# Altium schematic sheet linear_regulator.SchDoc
size A3
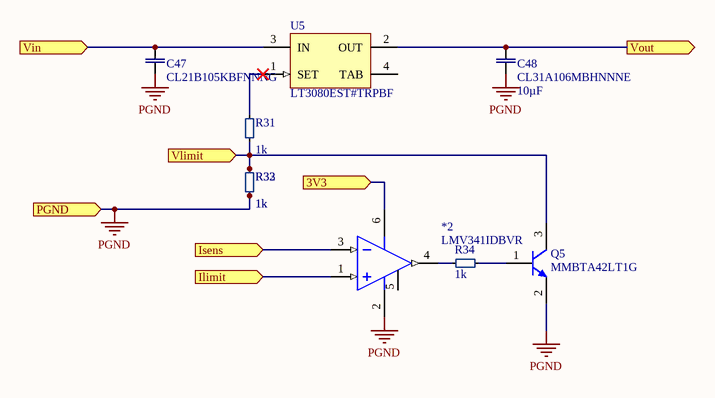
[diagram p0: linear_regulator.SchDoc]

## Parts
*2  LMV341IDBVR  [SOT95P280X145-6N]
C47  CL21B105KBFNNNG  [CAP0805]
C48  CL31A106MBHNNNE  Capacitance: 10µF  [Chip2PinSM127P600-8N]
Q5  MMBTA42LT1G  [ONSC-SOT-23-3-318-08_V]
R31  Resistance: 1k  [SMD_0402(1005)_M]  (hidden comment: RC0402FR-071KL)
R32  Resistance: 1k  [SMD_0402(1005)_M]  (hidden comment: RC0402FR-071KL)
R33  Resistance: 1k  [SMD_0402(1005)_M]  (hidden comment: RC0402FR-071KL)
R34  Resistance: 1k  [SMD_0402(1005)_M]  (hidden comment: RC0402FR-071KL)
U5  LT3080EST#TRPBF  [LT-ST-3-SOT-223_M]

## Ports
3V3 (in), Ilimit (in), Isens (in), PGND (in), Vin (in), Vlimit (in), Vout (out)

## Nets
PGND: *2.2(VEE/GND) C47.1 C48.1 Q5.2(E) R32.1 R33.1 ; port PGND
3V3: *2.6(VCC) ; port 3V3
Ilimit: *2.1(IN1+) ; port Ilimit
Isens: *2.3(IN1-) ; port Isens
Vin: C47.2 U5.3(IN) ; port Vin
Vlimit: Q5.3(C) R31.1 R32.2 R33.2 ; port Vlimit
Vout: C48.2 U5.2(OUT) ; port Vout
Net*2_4: *2.4(OUT1) R34.2
NetQ5_1: Q5.1(B) R34.1
NetR31_2: R31.2 U5.1(SET)

Not connected (* = marked no-connect by the designer): *2 5(!SHDN); U5 4(TAB)

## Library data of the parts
*2 = CMP-ROOT-00000-1: Single Rail-To-Rail Output CMOS Operational Amplifier with Shutdown 6-SOT-23 -40 to 125; Voltage Gain: 116dB; Output Current: 32mA; Number of Channels: 1; Common Mode Rejection Ratio: 56dB; Input Offset Voltage (Vos): 250uV; Bandwidth: 1MHz; Max Supply Voltage: 5.5V; Max Frequency: 1kHz; Output Current per Channel: 113mA; Operating Supply Current: 107uA; Slew Rate: 1V/µs; Input Bias Current: 200pA; Nominal Supply Current: 170uA; Min Supply Voltage: 2.5V
C47 = CMP-0001-00012-4: SAMSUNG ELECTRO-MECHANICS - CL21B105KBFNNNG - MLCC CAPACITORS; Voltage Rating: 50V; Dielectric: X7R; Material: Ceramic; Capacitance: 1µF; Tolerance: 10%
C48 = CMP-0001-00015-2: CAP CER 10UF 50V X5R 1206; Capacitor Type: Ceramic; Tolerance: 20%
Q5 = CMP-ROOT-00016-1: Trans GP BJT NPN 300V 0.5A Automotive 3-Pin SOT-23 T/R; Frequency: 50MHz; Emitter Base Voltage (VEBO): 6V; Number of Elements: 1; Max Collector Current: 500mA; Power Dissipation: 300mW; Max Power Dissipation: 225mW; Collector Emitter Saturation Voltage: 500mV; Element Configuration: Single; hFE Min: 25
R31-R34 = CMP-001-0000-7: Surface Mount Chip Resistor, Thick Film, RC Series, 1 kohm, 62.5 mW, 1%, 50 V, 0402 [1005 Metric]; Temperature Coefficient: 100ppm/°C; Value: 1k; Voltage Rating: 50V; Power Rating: 62.5mW
U5 = CMP-00005-1: IC REG LIN POS ADJ 1.1A SOT223-3; Operating Supply Current: 300uA; Quiescent Current: 500uA; Number of Regulators: 1; Output Voltage Accuracy: 1%; Min Input Voltage: 1.2V; Polarity: Positive; Dropout Voltage: 1.35V; Output Voltage: 36V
